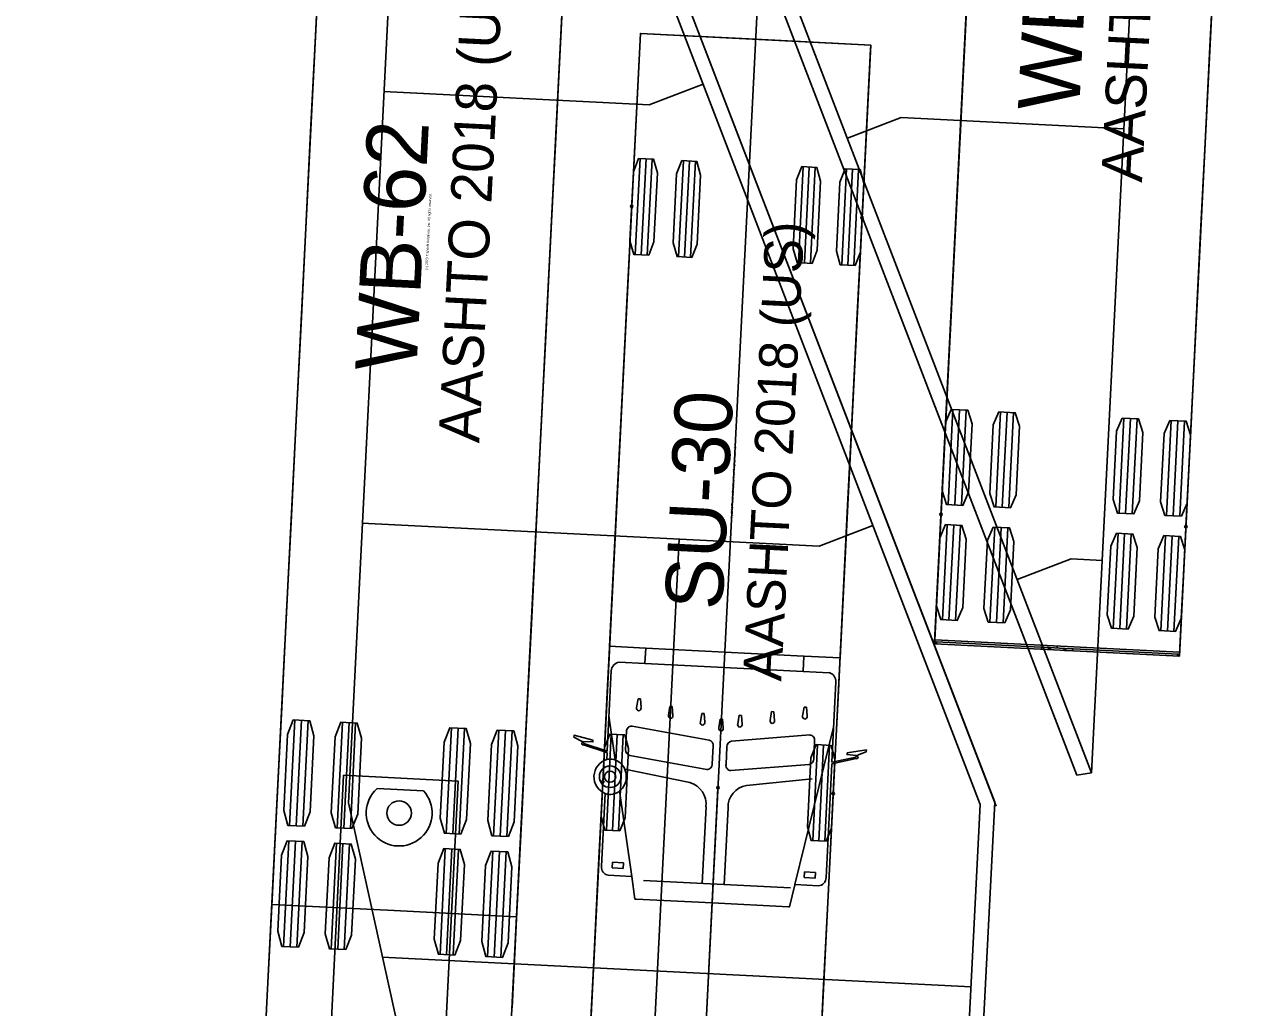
# Model space of a CAD drawing. Extents: x 260275 to 261282, y 610916 to 614143.
# Drawn here: x 261019.98 to 261062.63, y 612059.11 to 612093.2 of the extents above; entities that cross this region are included whole.
import ezdxf

# ---------------------------------------------------------------- set-up
doc = ezdxf.new("R2010")
doc.units = 0
for name, color, linetype in [('GE_X_Alignment', 7, 'Continuous'), ('PV_P_Curb', 7, 'Continuous'), ('PV_P_EOP', 7, 'Continuous'), ('PV_P_Joint', 7, 'Continuous'), ('TopoDOT_Transients', 7, 'Continuous'), ('UT_X_Water_Cells', 7, 'Continuous')]:
    doc.layers.add(name, color=color, linetype=linetype)

msp = doc.modelspace()

# ---------------------------------------------------------------- linework, layer by layer
at = {"layer": 'GE_X_Alignment'}
msp.add_line((260986.249, 610915.954), (261148.276, 614142.838), dxfattribs=at)
at = {"layer": 'PV_P_Curb'}
for p, q in [((261034.244, 612116.627), (261053.627, 612066.228)), ((261037.345, 612116.921), (261056.48, 612067.167)), ((261034.545, 612115.844), (261053.68, 612066.09)), ((261056.48, 612067.167), (261056.985, 612067.248)), ((261049.53, 611984.642), (261053.627, 612066.228))]:
    msp.add_line(p, q, dxfattribs=at)
at = {"layer": 'PV_P_EOP'}
for p, q in [((261037.86, 612116.976), (261056.985, 612067.248)), ((261031.212, 612066.209), (261033.739, 612116.547)), ((261033.739, 612116.547), (261053.122, 612066.147)), ((261056.985, 612067.248), (261059.122, 612109.815)), ((261045.801, 612000.096), (261031.212, 612066.209)), ((261049.031, 611984.667), (261053.122, 612066.147))]:
    msp.add_line(p, q, dxfattribs=at)
at = {"layer": 'PV_P_Joint'}
for p, q in [((261041.645, 612090.418), (261043.512, 612091.136)), ((261032.429, 612090.881), (261041.645, 612090.418)), ((261050.385, 612089.979), (261048.518, 612089.262)), ((261050.385, 612089.979), (261058.117, 612089.591)), ((261031.677, 612075.9), (261047.535, 612075.104)), ((261047.535, 612075.104), (261049.402, 612075.822)), ((261040.428, 612030.404), (261042.684, 612075.347)), ((261056.275, 612074.665), (261054.408, 612073.947)), ((261056.275, 612074.665), (261057.369, 612074.61)), ((261032.384, 612060.846), (261052.805, 612059.82))]:
    msp.add_line(p, q, dxfattribs=at)
at = {"layer": 'TopoDOT_Transients'}
for p, q in [((261052.178, 612079.846), (261052.013, 612076.55)), ((261052.407, 612079.834), (261052.242, 612076.538)), ((261052.636, 612079.823), (261052.47, 612076.527)), ((261053.826, 612079.763), (261053.661, 612076.467)), ((261054.055, 612079.751), (261053.89, 612076.456)), ((261054.284, 612079.74), (261054.118, 612076.444)), ((261058.104, 612079.548), (261057.939, 612076.252)), ((261058.333, 612079.537), (261058.167, 612076.241)), ((261058.562, 612079.525), (261058.396, 612076.229)), ((261059.752, 612079.465), (261059.586, 612076.17)), ((261059.981, 612079.454), (261059.815, 612076.158)), ((261060.21, 612079.442), (261060.044, 612076.147)), ((261051.978, 612075.851), (261051.812, 612072.555)), ((261052.206, 612075.839), (261052.041, 612072.543)), ((261052.435, 612075.828), (261052.27, 612072.532)), ((261053.626, 612075.768), (261053.46, 612072.472)), ((261053.854, 612075.756), (261053.689, 612072.461)), ((261054.083, 612075.745), (261053.918, 612072.449)), ((261057.903, 612075.553), (261057.738, 612072.257)), ((261058.132, 612075.542), (261057.967, 612072.246)), ((261058.361, 612075.53), (261058.196, 612072.234)), ((261059.551, 612075.47), (261059.386, 612072.175)), ((261059.78, 612075.459), (261059.615, 612072.163)), ((261060.009, 612075.447), (261059.844, 612072.152)), ((261060.037, 612071.432), (261051.548, 612071.858)), ((261055.524, 612071.588), (261055.258, 612071.601)), ((261055.53, 612071.588), (261056.052, 612071.562)), ((261055.789, 612071.575), (261055.792, 612071.645)), ((261056.319, 612071.548), (261056.054, 612071.561))]:
    msp.add_line(p, q, dxfattribs=at)
for points in [[(261051.548, 612071.863), (261074.206, 612523.277)], [(261082.631, 612521.243), (261060.03, 612071.291), (261051.541, 612071.717), (261051.548, 612071.863), (261051.548, 612071.863)], [(261060.011, 612071.363), (261060.033, 612071.362), (261062.437, 612119.231), (261058.192, 612119.444), (261053.948, 612119.657), (261051.544, 612071.788), (261051.567, 612071.787)], [(261051.766, 612076.212), (261051.933, 612079.541), (261052.101, 612082.871), (261052.268, 612086.2), (261052.435, 612089.53), (261052.602, 612092.859), (261052.769, 612096.189), (261052.937, 612099.519), (261053.104, 612102.848), (261053.271, 612106.178), (261053.438, 612109.507), (261053.605, 612112.837)], [(261060.256, 612075.785), (261060.423, 612079.115), (261060.59, 612082.445), (261060.757, 612085.774), (261060.924, 612089.104), (261061.091, 612092.433), (261061.259, 612095.763), (261061.426, 612099.092), (261061.593, 612102.422), (261061.76, 612105.751), (261061.927, 612109.081), (261062.095, 612112.41)], [(261051.591, 612071.785), (261051.592, 612071.786), (261055.222, 612071.603), (261055.258, 612071.601), (261055.255, 612071.531), (261055.256, 612071.531), (261055.522, 612071.518)], [(261056.048, 612071.491), (261056.314, 612071.478), (261056.316, 612071.478), (261056.319, 612071.548), (261056.355, 612071.546), (261059.986, 612071.364), (261059.987, 612071.364)]]:
    msp.add_lwpolyline(points, dxfattribs=at)
for points in [[(261052.121, 612079.849), (261052.693, 612079.82), (261052.842, 612079.35), (261052.723, 612076.977), (261052.527, 612076.524), (261051.956, 612076.553), (261051.807, 612077.023), (261051.926, 612079.396)], [(261053.769, 612079.766), (261054.341, 612079.737), (261054.49, 612079.267), (261054.37, 612076.894), (261054.175, 612076.441), (261053.604, 612076.47), (261053.455, 612076.94), (261053.574, 612079.313)], [(261058.047, 612079.551), (261058.619, 612079.522), (261058.768, 612079.052), (261058.648, 612076.679), (261058.453, 612076.226), (261057.882, 612076.255), (261057.733, 612076.725), (261057.852, 612079.098)], [(261059.695, 612079.468), (261060.267, 612079.44), (261060.415, 612078.969), (261060.296, 612076.596), (261060.101, 612076.144), (261059.53, 612076.172), (261059.381, 612076.642), (261059.5, 612079.015)], [(261051.921, 612075.854), (261052.492, 612075.825), (261052.641, 612075.355), (261052.522, 612072.982), (261052.327, 612072.529), (261051.755, 612072.558), (261051.606, 612073.028), (261051.726, 612075.401)], [(261053.569, 612075.771), (261054.14, 612075.742), (261054.289, 612075.272), (261054.17, 612072.899), (261053.975, 612072.446), (261053.403, 612072.475), (261053.254, 612072.945), (261053.373, 612075.318)], [(261057.847, 612075.556), (261058.418, 612075.527), (261058.567, 612075.057), (261058.448, 612072.684), (261058.252, 612072.231), (261057.681, 612072.26), (261057.532, 612072.73), (261057.651, 612075.103)], [(261059.495, 612075.473), (261060.066, 612075.445), (261060.215, 612074.975), (261060.096, 612072.602), (261059.9, 612072.149), (261059.329, 612072.177), (261059.18, 612072.647), (261059.299, 612075.02)]]:
    msp.add_lwpolyline(points, close=True, dxfattribs=at)
for centre, radius in [((261051.766, 612076.212), 0.0417), ((261060.256, 612075.785), 0.0417), ((261051.577, 612071.752), 0.0266), ((261059.997, 612071.329), 0.0266)]:
    msp.add_circle(centre, radius, dxfattribs=at)
for centre, radius, start, end in [((261051.577, 612071.752), 0.0363, 106.2023, 67.3649), ((261055.524, 612071.553), 0.0352, 86.913, 269.5524), ((261055.524, 612071.553), 0.0352, 267.1411, 87.7276), ((261056.05, 612071.526), 0.0352, 86.5234, 267.1099), ((261056.05, 612071.526), 0.0354, 271.417, 83.6025), ((261059.998, 612071.329), 0.0363, 106.8861, 68.0487)]:
    msp.add_arc(centre, radius, start, end, dxfattribs=at)
at = {"layer": 'UT_X_Water_Cells'}
for p, q in [((261041.163, 612085.226), (261041.33, 612088.555)), ((261041.371, 612085.216), (261041.539, 612088.545)), ((261041.579, 612085.205), (261041.747, 612088.534)), ((261042.661, 612085.151), (261042.829, 612088.48)), ((261042.869, 612085.14), (261043.037, 612088.469)), ((261043.078, 612085.13), (261043.245, 612088.459)), ((261046.823, 612084.942), (261046.99, 612088.271)), ((261047.031, 612084.931), (261047.198, 612088.26)), ((261047.239, 612084.921), (261047.406, 612088.25)), ((261048.321, 612084.867), (261048.488, 612088.196)), ((261048.529, 612084.856), (261048.696, 612088.185)), ((261048.737, 612084.846), (261048.904, 612088.175)), ((261041.525, 612071.571), (261047.01, 612071.295)), ((261041.498, 612071.04), (261046.983, 612070.764)), ((261041.207, 612069.513), (261041.258, 612069.81)), ((261041.258, 612069.81), (261041.341, 612069.806)), ((261041.341, 612069.806), (261041.361, 612069.505)), ((261040.251, 612069.224), (261040.468, 612067.691)), ((261042.312, 612069.247), (261042.363, 612069.544)), ((261042.363, 612069.544), (261042.446, 612069.54)), ((261042.446, 612069.54), (261042.467, 612069.239)), ((261043.419, 612069.008), (261043.47, 612069.306)), ((261043.47, 612069.306), (261043.552, 612069.302)), ((261043.552, 612069.302), (261043.573, 612069.001)), ((261044.714, 612068.943), (261044.765, 612069.241)), ((261044.765, 612069.241), (261044.847, 612069.237)), ((261044.847, 612069.237), (261044.868, 612068.936)), ((261045.839, 612069.056), (261045.89, 612069.367)), ((261045.89, 612069.367), (261045.972, 612069.363)), ((261045.972, 612069.363), (261045.993, 612069.048)), ((261046.965, 612069.224), (261047.016, 612069.521)), ((261047.016, 612069.521), (261047.099, 612069.517)), ((261047.099, 612069.517), (261047.119, 612069.216)), ((261029.176, 612065.417), (261029.36, 612069.079)), ((261029.405, 612065.405), (261029.588, 612069.067)), ((261029.633, 612065.394), (261029.817, 612069.056)), ((261030.824, 612065.334), (261031.007, 612068.996)), ((261031.052, 612065.322), (261031.236, 612068.985)), ((261031.281, 612065.311), (261031.465, 612068.973)), ((261034.602, 612065.144), (261034.786, 612068.806)), ((261034.831, 612065.133), (261035.015, 612068.795)), ((261035.06, 612065.121), (261035.244, 612068.783)), ((261043.724, 612068.381), (261041.051, 612068.867)), ((261044.058, 612068.808), (261044.109, 612069.105)), ((261044.109, 612069.105), (261044.191, 612069.101)), ((261044.191, 612069.101), (261044.212, 612068.8)), ((261048.042, 612068.833), (261046.701, 612063.366)), ((261036.25, 612065.061), (261036.434, 612068.724)), ((261036.479, 612065.05), (261036.663, 612068.712)), ((261036.708, 612065.039), (261036.892, 612068.701)), ((261040.16, 612065.251), (261040.328, 612068.58)), ((261040.368, 612065.241), (261040.536, 612068.57)), ((261040.576, 612065.23), (261040.744, 612068.559)), ((261040.859, 612068.674), (261040.828, 612068.058)), ((261044.502, 612068.342), (261047.21, 612068.558)), ((261047.382, 612068.347), (261047.351, 612067.731)), ((261043.834, 612067.555), (261043.865, 612068.171)), ((261044.309, 612067.531), (261044.34, 612068.147)), ((261047.318, 612064.892), (261047.485, 612068.221)), ((261047.526, 612064.881), (261047.693, 612068.21)), ((261047.734, 612064.871), (261047.901, 612068.2)), ((261040.97, 612067.849), (261043.643, 612067.363)), ((261047.189, 612067.537), (261044.481, 612067.321)), ((261043.057, 612066.905), (261040.802, 612067.366)), ((261045.018, 612066.807), (261047.296, 612067.038)), ((261044.031, 612066.726), (261023.69, 611661.632)), ((261033.821, 612066.615), (261032.206, 612066.696)), ((261040.619, 612066.616), (261041.038, 612063.65)), ((261040.116, 612066.525), (261039.989, 612064.006)), ((261043.481, 612063.404), (261043.615, 612066.069)), ((261044.245, 612063.366), (261044.379, 612066.031)), ((261028.965, 612061.222), (261029.149, 612064.884)), ((261029.194, 612061.21), (261029.378, 612064.873)), ((261029.423, 612061.199), (261029.607, 612064.861)), ((261030.613, 612061.139), (261030.797, 612064.801)), ((261030.842, 612061.128), (261031.026, 612064.79)), ((261031.071, 612061.116), (261031.255, 612064.778)), ((261034.392, 612060.95), (261034.575, 612064.612)), ((261034.62, 612060.938), (261034.804, 612064.6)), ((261034.849, 612060.927), (261035.033, 612064.589)), ((261036.039, 612060.867), (261036.223, 612064.529)), ((261036.268, 612060.855), (261036.452, 612064.517)), ((261036.497, 612060.844), (261036.681, 612064.506)), ((261040.372, 612064.14), (261040.362, 612063.946)), ((261040.75, 612064.121), (261040.372, 612064.14)), ((261040.741, 612063.927), (261040.75, 612064.121)), ((261040.362, 612063.946), (261040.741, 612063.927)), ((261047.024, 612063.611), (261047.034, 612063.805)), ((261047.402, 612063.592), (261047.024, 612063.611)), ((261047.034, 612063.805), (261047.412, 612063.786)), ((261047.412, 612063.786), (261047.402, 612063.592)), ((261041.447, 612063.506), (261046.545, 612063.25))]:
    msp.add_line(p, q, dxfattribs=at)
for points in [[(261009.34, 611680.102), (261030.965, 612110.617), (261039.455, 612110.191), (261039.447, 612110.045), (261039.447, 612110.045)], [(261030.984, 612110.546), (261030.962, 612110.547), (261028.558, 612062.678), (261032.803, 612062.464), (261037.048, 612062.251), (261039.451, 612110.12), (261039.429, 612110.122)], [(261039.447, 612110.045), (261018.12, 611685.301)], [(261030.74, 612106.123), (261030.573, 612102.794), (261030.406, 612099.466), (261030.238, 612096.137), (261030.071, 612092.808), (261029.904, 612089.48), (261029.737, 612086.151), (261029.57, 612082.822), (261029.403, 612079.494), (261029.236, 612076.165), (261029.068, 612072.836), (261028.901, 612069.508), (261028.734, 612066.179), (261028.567, 612062.85), (261028.4, 612059.522), (261028.233, 612056.193)], [(261039.229, 612105.697), (261039.062, 612102.368), (261038.895, 612099.039), (261038.728, 612095.711), (261038.561, 612092.382), (261038.393, 612089.053), (261038.226, 612085.725), (261038.059, 612082.396), (261037.892, 612079.067), (261037.725, 612075.739), (261037.558, 612072.41), (261037.391, 612069.081), (261037.223, 612065.753), (261037.056, 612062.424), (261036.889, 612059.095)], [(261020.965, 611687.133), (261041.34, 612092.893), (261049.33, 612092.492), (261049.322, 612092.345), (261049.322, 612092.345)], [(261047.881, 612070.719), (261046.986, 612070.764), (261046.983, 612070.768), (261047.01, 612071.294), (261047.021, 612071.295), (261048.262, 612071.232), (261049.33, 612092.492), (261045.335, 612092.693), (261041.34, 612092.893), (261040.272, 612071.634), (261041.514, 612071.571), (261041.525, 612071.57), (261041.498, 612071.044), (261041.495, 612071.04), (261040.6, 612071.085)], [(261049.322, 612092.345), (261028.546, 611678.469)], [(261041.039, 612086.901), (261040.872, 612083.572), (261040.705, 612080.244), (261040.537, 612076.915), (261040.37, 612073.586), (261040.203, 612070.258), (261040.036, 612066.929), (261039.869, 612063.601), (261039.702, 612060.272), (261039.535, 612056.943), (261039.367, 612053.615), (261039.2, 612050.286), (261039.033, 612046.958), (261038.866, 612043.629), (261038.699, 612040.3), (261038.532, 612036.972), (261038.365, 612033.643), (261038.198, 612030.314), (261038.03, 612026.986), (261037.863, 612023.657), (261037.696, 612020.329), (261037.529, 612017), (261037.362, 612013.671)], [(261049.029, 612086.5), (261048.862, 612083.171), (261048.694, 612079.843), (261048.527, 612076.514), (261048.36, 612073.185), (261048.193, 612069.857), (261048.026, 612066.528), (261047.859, 612063.199), (261047.692, 612059.871), (261047.525, 612056.542), (261047.357, 612053.214), (261047.19, 612049.885), (261047.023, 612046.556), (261046.856, 612043.228), (261046.689, 612039.899), (261046.522, 612036.57), (261046.355, 612033.242), (261046.187, 612029.913), (261046.02, 612026.585), (261045.853, 612023.256), (261045.686, 612019.927), (261045.519, 612016.599)], [(261040.33, 612070.783), (261040.191, 612068.012), (261040.185, 612068), (261039.38, 612068.261), (261039.38, 612068.261)], [(261048.812, 612067.787), (261048.812, 612067.787), (261047.985, 612067.609), (261047.981, 612067.621), (261048.12, 612070.391)], [(261039.369, 612068.281), (261039.371, 612068.326), (261039.371, 612068.326), (261039.689, 612068.319), (261039.692, 612068.319), (261039.694, 612068.374), (261039.691, 612068.376), (261039.043, 612068.548), (261039.04, 612068.548), (261039.037, 612068.483), (261039.325, 612068.337), (261039.325, 612068.336), (261039.324, 612068.289)], [(261039.36, 612068.214), (261039.361, 612068.214), (261040.18, 612067.946), (261040.187, 612067.934), (261040.175, 612067.706)], [(261048.871, 612067.81), (261048.874, 612067.857), (261048.874, 612067.857), (261049.175, 612067.974), (261049.179, 612068.039), (261049.176, 612068.039), (261048.514, 612067.933), (261048.511, 612067.932), (261048.508, 612067.876), (261048.51, 612067.876), (261048.827, 612067.851), (261048.827, 612067.851), (261048.825, 612067.807)], [(261047.78, 612063.615), (261047.977, 612067.543), (261047.984, 612067.554), (261048.826, 612067.739), (261048.827, 612067.739)], [(261035.116, 612056.341), (261034.487, 612056.372), (261035.018, 612066.959), (261031.049, 612067.158), (261030.518, 612056.572), (261029.888, 612056.603)], [(261040.036, 612066.926), (261039.869, 612063.598), (261039.702, 612060.269), (261039.534, 612056.94), (261039.367, 612053.612), (261039.2, 612050.283), (261039.033, 612046.954), (261038.866, 612043.626), (261038.699, 612040.297), (261038.532, 612036.969), (261038.364, 612033.64), (261038.197, 612030.311), (261038.03, 612026.983), (261037.863, 612023.654), (261037.696, 612020.325), (261037.529, 612016.997), (261037.362, 612013.668)], [(261048.026, 612066.525), (261047.859, 612063.196), (261047.692, 612059.868), (261047.524, 612056.539), (261047.357, 612053.21), (261047.19, 612049.882), (261047.023, 612046.553), (261046.856, 612043.225), (261046.689, 612039.896), (261046.522, 612036.567), (261046.354, 612033.239), (261046.187, 612029.91), (261046.02, 612026.582), (261045.853, 612023.253), (261045.686, 612019.924), (261045.519, 612016.596)], [(261040.227, 612063.691), (261041.034, 612063.65), (261041.038, 612063.645), (261041.148, 612062.867), (261041.19, 612062.863), (261043.83, 612062.731), (261046.471, 612062.598), (261046.513, 612062.598), (261046.7, 612063.361), (261046.705, 612063.365), (261047.511, 612063.325)]]:
    msp.add_lwpolyline(points, dxfattribs=at)
for points in [[(261041.631, 612085.202), (261041.112, 612085.229), (261040.979, 612085.702), (261041.099, 612088.099), (261041.279, 612088.558), (261041.798, 612088.532), (261041.931, 612088.058), (261041.811, 612085.661)], [(261043.129, 612085.127), (261042.61, 612085.153), (261042.477, 612085.627), (261042.597, 612088.024), (261042.777, 612088.482), (261043.296, 612088.456), (261043.429, 612087.982), (261043.309, 612085.585)], [(261047.291, 612084.918), (261046.771, 612084.944), (261046.638, 612085.418), (261046.759, 612087.815), (261046.938, 612088.274), (261047.458, 612088.247), (261047.591, 612087.774), (261047.47, 612085.377)], [(261048.789, 612084.843), (261048.269, 612084.869), (261048.136, 612085.343), (261048.257, 612087.74), (261048.437, 612088.198), (261048.956, 612088.172), (261049.089, 612087.698), (261048.969, 612085.301)], [(261029.69, 612065.391), (261029.119, 612065.42), (261028.973, 612065.941), (261029.105, 612068.578), (261029.303, 612069.082), (261029.874, 612069.053), (261030.02, 612068.532), (261029.888, 612065.895)], [(261031.338, 612065.308), (261030.767, 612065.337), (261030.62, 612065.858), (261030.753, 612068.495), (261030.951, 612068.999), (261031.522, 612068.97), (261031.668, 612068.449), (261031.536, 612065.812)], [(261035.117, 612065.118), (261034.545, 612065.147), (261034.399, 612065.668), (261034.531, 612068.305), (261034.729, 612068.809), (261035.301, 612068.78), (261035.447, 612068.259), (261035.315, 612065.622)], [(261036.765, 612065.036), (261036.193, 612065.064), (261036.047, 612065.586), (261036.179, 612068.222), (261036.377, 612068.726), (261036.948, 612068.698), (261037.095, 612068.176), (261036.962, 612065.54)], [(261040.628, 612065.228), (261040.109, 612065.254), (261039.976, 612065.728), (261040.096, 612068.125), (261040.276, 612068.583), (261040.795, 612068.557), (261040.928, 612068.083), (261040.808, 612065.686)], [(261047.786, 612064.868), (261047.266, 612064.894), (261047.133, 612065.368), (261047.254, 612067.765), (261047.434, 612068.223), (261047.953, 612068.197), (261048.086, 612067.723), (261047.966, 612065.326)], [(261029.48, 612061.196), (261028.908, 612061.225), (261028.762, 612061.746), (261028.894, 612064.383), (261029.092, 612064.887), (261029.663, 612064.858), (261029.81, 612064.337), (261029.677, 612061.7)], [(261031.127, 612061.113), (261030.556, 612061.142), (261030.41, 612061.663), (261030.542, 612064.3), (261030.74, 612064.804), (261031.311, 612064.775), (261031.458, 612064.254), (261031.325, 612061.617)], [(261034.906, 612060.924), (261034.335, 612060.952), (261034.188, 612061.474), (261034.321, 612064.11), (261034.519, 612064.614), (261035.09, 612064.586), (261035.236, 612064.064), (261035.104, 612061.428)], [(261036.554, 612060.841), (261035.983, 612060.87), (261035.836, 612061.391), (261035.969, 612064.028), (261036.167, 612064.532), (261036.738, 612064.503), (261036.884, 612063.982), (261036.752, 612061.345)]]:
    msp.add_lwpolyline(points, close=True, dxfattribs=at)
for centre, radius in [((261041.039, 612086.901), 0.0417), ((261049.029, 612086.5), 0.0417), ((261040.29, 612067.108), 0.374), ((261040.29, 612067.108), 0.193), ((261040.036, 612066.926), 0.0417), ((261044.031, 612066.726), 0.0417), ((261032.973, 612065.848), 0.424), ((261048.026, 612066.525), 0.0417)]:
    msp.add_circle(centre, radius, dxfattribs=at)
for centre, radius, start, end in [((261040.652, 612070.766), 0.323, 99.2771, 177.1255), ((261047.798, 612070.408), 0.323, 357.1255, 74.9739), ((261041.295, 612069.49), 0.091, 165.4421, 259.6059), ((261041.272, 612069.491), 0.0909, 274.6094, 8.8446), ((261042.401, 612069.224), 0.091, 165.4421, 259.6059), ((261042.377, 612069.225), 0.0909, 274.6094, 8.8446), ((261047.053, 612069.201), 0.0909, 165.4064, 259.6416), ((261047.03, 612069.202), 0.091, 274.6451, 8.8089), ((261041.043, 612068.683), 0.184, 87.7181, 182.5893), ((261043.507, 612068.986), 0.091, 165.4421, 259.6059), ((261043.483, 612068.987), 0.0909, 274.6094, 8.8446), ((261044.146, 612068.785), 0.091, 165.4421, 259.6059), ((261044.122, 612068.786), 0.091, 274.6451, 8.8089), ((261044.802, 612068.921), 0.0909, 165.4064, 259.6416), ((261044.778, 612068.922), 0.091, 274.6451, 8.8089), ((261045.927, 612069.047), 0.0909, 165.4064, 259.6416), ((261045.903, 612069.048), 0.091, 274.6451, 8.8089), ((261043.674, 612068.195), 0.193, 353.0637, 74.988), ((261044.533, 612068.151), 0.193, 99.263, 181.1873), ((261047.199, 612068.373), 0.184, 351.6617, 86.5329), ((261039.343, 612068.252), 0.0418, 117.6187, 294.6336), ((261039.337, 612068.252), 0.0434, 11.039, 41.7118), ((261041.019, 612068.035), 0.193, 173.0686, 254.9831), ((261040.358, 612067.105), 0.628, 106.8788, 247.3705), ((261040.295, 612067.195), 0.524, 49.3845, 103.1846), ((261040.222, 612067.119), 0.63, 356.4803, 48.8831), ((261043.65, 612067.547), 0.184, 267.7236, 2.5838), ((261044.492, 612067.505), 0.184, 171.6672, 266.5274), ((261047.158, 612067.727), 0.193, 279.2679, 1.1824), ((261048.854, 612067.775), 0.0434, 132.5392, 163.212), ((261048.848, 612067.775), 0.0418, 239.6174, 56.6324), ((261040.222, 612067.104), 0.629, 309.1711, 357.8604), ((261032.973, 612065.848), 1.143, 132.1255, 42.1255), ((261040.286, 612067.022), 0.526, 251.0707, 309.3167), ((261042.847, 612066.161), 0.773, 353.1509, 74.235), ((261045.152, 612066.045), 0.773, 100.016, 181.1001), ((261040.269, 612063.969), 0.282, 172.4977, 261.5771), ((261047.498, 612063.606), 0.282, 272.6739, 1.7533)]:
    msp.add_arc(centre, radius, start, end, dxfattribs=at)

# ---------------------------------------------------------------- texts
at = {"layer": 'TopoDOT_Transients'}
for s, height, p in [('AASHTO 2018 (US)', 1.41667, (261058.734, 612087.712)), ('WB-62', 2.125, (261056.553, 612090.177))]:
    msp.add_text(s, height=height, rotation=87.1255, dxfattribs=at).set_placement(p)
at = {"layer": 'UT_X_Water_Cells'}
for s, height, p in [('AASHTO 2018 (US)', 1.41667, (261035.752, 612078.672)), ('WB-62', 2.125, (261033.57, 612081.137)), ('(c) 2023 Transoft Solutions, Inc. All rights reserved.', 0.085, (261033.962, 612084.694)), ('AASHTO 2018 (US)', 1.33333, (261046.225, 612070.406)), ('SU-30', 2, (261044.179, 612072.869)), ('(c) 2023 Transoft Solutions, Inc. All rights reserved.', 0.08, (261044.54, 612076.074))]:
    msp.add_text(s, height=height, rotation=87.1255, dxfattribs=at).set_placement(p)

doc.saveas('drawing.dxf')
